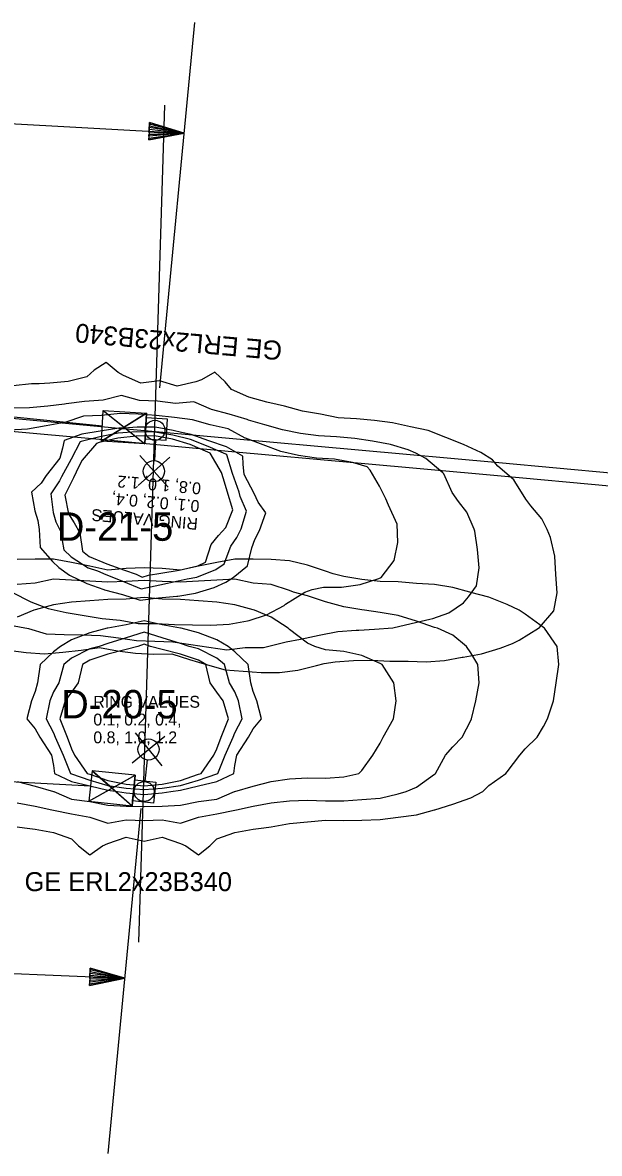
# Model space of a CAD drawing. Extents: x 1638506 to 1658005, y 834807 to 846788.
# Drawn here: x 1642969.6 to 1643212.7, y 842001.9 to 842479 of the extents above; entities that cross this region are included whole.
import ezdxf

# ---------------------------------------------------------------- set-up
doc = ezdxf.new("R2010")
doc.units = 0
for name, color, linetype in [('Default', 7, 'Continuous'), ('Exist Guardrail', 7, 'Continuous'), ('Old_Level_1', 7, 'Continuous'), ('Old_Level_2', 7, 'Continuous')]:
    doc.layers.add(name, color=color, linetype=linetype)

msp = doc.modelspace()

# ---------------------------------------------------------------- linework, layer by layer
at = {"layer": 'Default'}
for p, q in [((1643027.37, 842324.84), (1643042.12, 842478.96)), ((1642941.72, 842437.69), (1643037.67, 842432.39)), ((1642769.13, 842332.63), (1643003.18, 842308.79)), ((1643002.81, 842302.32), (1643021.8, 842314.24)), ((1643003.54, 842315.26), (1643021.07, 842301.3)), ((1643025.65, 842303.07), (1643025.15, 842294.14)), ((1643018.23, 842283.74), (1643031.58, 842295.64)), ((1643018.97, 842296.35), (1643030.87, 842283.03)), ((1643021.91, 842293.06), (1643021.91, 842293.06)), ((1643024.9, 842289.67), (1643024.9, 842289.67)), ((1643015.73, 842166.71), (1643029.59, 842177.98)), ((1643017, 842179.28), (1643028.3, 842165.42)), ((1642764.55, 842169.54), (1642998.17, 842156.92)), ((1643019.15, 842169.5), (1643019.15, 842169.5)), ((1643021.27, 842159.02), (1643022.19, 842167.92)), ((1643022.65, 842172.36), (1643022.65, 842172.36)), ((1642998.84, 842163.37), (1643015.7, 842148.6)), ((1642997.51, 842150.47), (1643017.03, 842161.49)), ((1643005.64, 842001.93), (1643019.57, 842147.37)), ((1642900.05, 842080.54), (1643012.72, 842075.81))]:
    msp.add_line(p, q, dxfattribs=at)
for points in [[(1643022.89, 842433.21), (1643022.93, 842433.95), (1643037.67, 842432.39), (1643022.97, 842434.64), (1643023.01, 842435.38), (1643037.67, 842432.39), (1643023.05, 842436.12), (1643023.09, 842436.85), (1643037.67, 842432.39), (1643022.74, 842429.51), (1643022.73, 842430.25), (1643037.67, 842432.39), (1643022.82, 842430.99), (1643022.81, 842431.73), (1643037.67, 842432.39), (1643022.85, 842432.47), (1643023.09, 842436.85), (1643022.74, 842429.51), (1643037.67, 842432.39), (1643023.09, 842436.85)], [(1643022.89, 842433.21), (1643022.93, 842433.95), (1643037.67, 842432.39), (1643022.97, 842434.64), (1643023.01, 842435.38), (1643037.67, 842432.39), (1643023.05, 842436.12), (1643023.09, 842436.85), (1643037.67, 842432.39), (1643022.74, 842429.51), (1643022.73, 842430.25), (1643037.67, 842432.39), (1643022.82, 842430.99), (1643022.81, 842431.73), (1643037.67, 842432.39), (1643022.85, 842432.47), (1643023.09, 842436.85), (1643022.74, 842429.51), (1643037.67, 842432.39), (1643023.09, 842436.85)], [(1642997.93, 842076.43), (1642997.97, 842077.17), (1643012.72, 842075.81), (1642997.99, 842077.86), (1642998.03, 842078.6), (1643012.72, 842075.81), (1642998.06, 842079.34), (1642998.09, 842080.08), (1643012.72, 842075.81), (1642997.83, 842072.73), (1642997.81, 842073.47), (1643012.72, 842075.81), (1642997.89, 842074.21), (1642997.87, 842074.95), (1643012.72, 842075.81), (1642997.9, 842075.69), (1642998.09, 842080.08), (1642997.83, 842072.73), (1643012.72, 842075.81), (1642998.09, 842080.08)]]:
    msp.add_lwpolyline(points, dxfattribs=at)
for points in [[(1643003.54, 842315.26), (1643021.8, 842314.24), (1643021.07, 842301.3), (1643002.81, 842302.32)], [(1643012.31, 842308.28), (1643002.81, 842302.32), (1643003.54, 842315.26)], [(1643012.31, 842308.28), (1643021.07, 842301.3), (1643021.8, 842314.24)], [(1643021.69, 842312.22), (1643021.19, 842303.32), (1643030.12, 842302.82), (1643030.62, 842311.72)], [(1642997.51, 842150.47), (1643015.7, 842148.6), (1643017.03, 842161.49), (1642998.84, 842163.37)], [(1643007.27, 842155.98), (1642998.84, 842163.37), (1642997.51, 842150.47)], [(1643007.27, 842155.98), (1643017.03, 842161.49), (1643015.7, 842148.6)], [(1643015.9, 842150.61), (1643016.82, 842159.48), (1643025.72, 842158.56), (1643024.8, 842149.69)]]:
    msp.add_lwpolyline(points, close=True, dxfattribs=at)
for centre in [(1643024.91, 842289.7), (1643022.65, 842172.33)]:
    msp.add_circle(centre, 4.47, dxfattribs=at)
at = {"layer": 'Exist Guardrail'}
msp.add_lwpolyline([(1642855.97, 842316.64), (1642901.48, 842312.43), (1642956.93, 842307.27), (1643008.14, 842302.6), (1643057.7, 842298.05), (1643110.69, 842293.31), (1643169.76, 842287.95), (1643218.45, 842283.37)], dxfattribs=at)
at = {"layer": 'Old_Level_1'}
for points in [[(1642963.51, 842214.19), (1642971.11, 842213.29), (1642978.73, 842212.63), (1642986.47, 842213.34), (1642994.23, 842214.26), (1643002, 842215.3), (1643009.56, 842213.88), (1643017.15, 842212.92), (1643024.8, 842212.55), (1643032.48, 842212.63), (1643039.96, 842210.25), (1643047.44, 842208.01), (1643054.94, 842205.96), (1643062.56, 842205.29), (1643070.2, 842204.85), (1643077.87, 842204.73), (1643085.64, 842205.81), (1643093.49, 842207.74), (1643096.73, 842208.6), (1643101.31, 842209.35), (1643109.04, 842209.9), (1643116.73, 842210.02), (1643124.37, 842209.56), (1643132.05, 842209.62), (1643139.7, 842209.3), (1643147.43, 842209.87), (1643154.79, 842211.2), (1643155.23, 842211.3), (1643163.04, 842212.71), (1643170.92, 842215.07), (1643176.12, 842217.02), (1643178.9, 842218.45), (1643187.01, 842223.43), (1643187.44, 842223.71), (1643193.49, 842230.86), (1643194.89, 842238.41), (1643194.33, 842246.14), (1643193.94, 842253.85), (1643192.11, 842261.69), (1643190.65, 842265.06), (1643188.44, 842269.69), (1643183.85, 842275.09), (1643181.74, 842277.96), (1643177.08, 842285.41), (1643176.63, 842286.09), (1643169.96, 842291.78), (1643167.58, 842294.56), (1643162.79, 842297.61), (1643155.4, 842300.98), (1643148.04, 842303.95), (1643147.98, 842303.97), (1643140.56, 842306.86), (1643133.02, 842308.48), (1643125.48, 842310.07), (1643117.89, 842311.07), (1643110.27, 842311.78), (1643102.64, 842312.3), (1643095.09, 842313.8), (1643087.53, 842315.11), (1643080.03, 842317.18), (1643076.94, 842317.84), (1643072.5, 842318.87), (1643065, 842320.92), (1643057.61, 842324.23), (1643054.99, 842327.44), (1643050.57, 842331.56), (1643044.94, 842328.32), (1643042.53, 842327.47), (1643034.68, 842325.55), (1643027.21, 842327.9), (1643019.44, 842326.89), (1643012.05, 842330.14), (1643009.83, 842331.4), (1643004.84, 842335.57), (1642999.78, 842332.27), (1642996.64, 842329.57), (1642988.79, 842327.59), (1642981.04, 842326.87), (1642976.49, 842326.63), (1642973.33, 842326.51), (1642965.59, 842325.78)], [(1642964.43, 842224.72), (1642971.99, 842223.38), (1642979.47, 842221.07), (1642987.12, 842220.78), (1642994.79, 842220.62), (1643002.45, 842220.4), (1643010.04, 842219.41), (1643017.63, 842218.35), (1643025.28, 842218.08), (1643032.93, 842217.73), (1643040.51, 842216.62), (1643048.09, 842215.44), (1643055.68, 842214.4), (1643063.44, 842215.38), (1643071.12, 842215.38), (1643078.96, 842217.25), (1643080.72, 842217.68), (1643086.78, 842218.8), (1643094.61, 842220.59), (1643102.43, 842222.1), (1643110.15, 842222.6), (1643111.26, 842222.69), (1643117.87, 842223.08), (1643125.6, 842223.63), (1643133.43, 842225.4), (1643141.28, 842227.33), (1643142.55, 842227.63), (1643149.18, 842229.92), (1643155.38, 842234.19), (1643157.46, 842236.74), (1643160.9, 842241.39), (1643162.04, 842248.97), (1643161.27, 842256.71), (1643160.23, 842264.48), (1643159.95, 842265.21), (1643156.89, 842272.45), (1643153.3, 842276.91), (1643150.63, 842280.68), (1643147.11, 842288.67), (1643146.68, 842289.07), (1643139.53, 842295.09), (1643135.38, 842297.37), (1643132.16, 842298.67), (1643124.69, 842301.05), (1643117.13, 842302.35), (1643109.55, 842303.57), (1643101.93, 842304.25), (1643094.29, 842304.62), (1643086.69, 842305.59), (1643079.15, 842307.14), (1643071.65, 842309.21), (1643064.86, 842311.22), (1643064.17, 842311.52), (1643056.69, 842313.73), (1643049.18, 842315.74), (1643041.79, 842318.97), (1643034.04, 842318.24), (1643026.45, 842319.2), (1643018.8, 842319.57), (1643011.3, 842321.64), (1643003.46, 842319.74), (1642995.72, 842319.06), (1642987.96, 842318.19), (1642987.24, 842318.01), (1642980.2, 842317.21), (1642972.46, 842316.47), (1642964.76, 842316.26)], [(1642965.63, 842238.46), (1642972.41, 842234.84), (1642972.97, 842234.62), (1642980.41, 842231.83), (1642987.94, 842230.1), (1642995.51, 842228.89), (1643003.08, 842227.64), (1643010.69, 842226.82), (1643018.24, 842225.42), (1643025.93, 842225.48), (1643033.56, 842224.98), (1643041.24, 842224.89), (1643048.9, 842224.77), (1643056.62, 842225.16), (1643064.42, 842226.62), (1643065.01, 842226.74), (1643072.32, 842229.13), (1643079.82, 842233.12), (1643080.4, 842233.63), (1643088.52, 842238.71), (1643091.65, 842239.77), (1643096.38, 842240.73), (1643104.06, 842240.81), (1643111.83, 842241.86), (1643119.74, 842244.52), (1643120.65, 842244.91), (1643126.23, 842252.1), (1643127.81, 842259.64), (1643127.42, 842267.35), (1643123.81, 842275.35), (1643122.68, 842278.05), (1643120.03, 842283.36), (1643116.05, 842290.1), (1643114.83, 842291.49), (1643108.67, 842293.45), (1643101.1, 842294.75), (1643093.47, 842295.27), (1643085.89, 842296.37), (1643078.36, 842298.08), (1643070.91, 842300.79), (1643063.48, 842303.62), (1643063.36, 842303.67), (1643056.15, 842307.54), (1643048.61, 842309.21), (1643041.12, 842311.35), (1643033.54, 842312.42), (1643025.93, 842313.26), (1643018.29, 842313.76), (1643010.64, 842314.01), (1643002.89, 842313.21), (1642995.18, 842312.88), (1642987.41, 842310.32), (1642987.27, 842310.29), (1642979.46, 842308.79), (1642971.66, 842307.42), (1642963.95, 842307.04)], [(1642974.71, 842273.03), (1642975.97, 842268.91), (1642976.57, 842265.19), (1642977.01, 842257.47), (1642982.13, 842251.56), (1642984.85, 842249.11), (1642989.32, 842245.92), (1642996.68, 842242.32), (1643003.81, 842239.77), (1643004.13, 842239.67), (1643011.64, 842237.66), (1643019.11, 842235.29), (1643026.88, 842236.32), (1643034.62, 842237), (1643034.95, 842237.05), (1643042.41, 842238.32), (1643050.29, 842240.59), (1643055.25, 842242.95), (1643058.34, 842244.89), (1643064.42, 842249.83), (1643066.2, 842257.35), (1643067.42, 842260.91), (1643069.39, 842264.75), (1643072.06, 842272.2), (1643068.8, 842276.67), (1643067.24, 842280.3), (1643062.9, 842288.36), (1643062.53, 842292.71), (1643062.38, 842296.08), (1643055.49, 842300.06), (1643048.03, 842302.58), (1643040.58, 842305.15), (1643036.58, 842306.02), (1643033.05, 842306.92), (1643025.49, 842308.26), (1643017.81, 842308.26), (1643014.18, 842307.98), (1643010.09, 842307.82), (1643002.31, 842306.58), (1642994.52, 842305.39), (1642987.05, 842302.67), (1642986.32, 842299.37), (1642985.2, 842295.15), (1642979.52, 842287.97), (1642977.35, 842284.67), (1642973.37, 842280.83), (1642974.71, 842273.03)], [(1642982.4, 842272.36), (1642983.61, 842268.37), (1642985.48, 842264.41), (1642986.96, 842256.6), (1642989.99, 842253.55), (1642997.27, 842249), (1643001.2, 842247.68), (1643004.7, 842246.17), (1643012.11, 842243.12), (1643019.53, 842240.07), (1643027.36, 842241.79), (1643035.18, 842243.51), (1643038.89, 842244.38), (1643042.99, 842245), (1643050.96, 842248.22), (1643054.47, 842250.7), (1643057.28, 842258.13), (1643059.81, 842261.7), (1643061.69, 842265.42), (1643063.89, 842272.91), (1643061.33, 842279.01), (1643060.79, 842280.86), (1643058.09, 842288.78), (1643055.61, 842296.67), (1643055.21, 842296.9), (1643047.82, 842300.17), (1643040.4, 842303.07), (1643032.88, 842304.95), (1643025.31, 842306.22), (1643017.64, 842306.29), (1643009.91, 842305.74), (1643002.1, 842304.17), (1642994.25, 842302.24), (1642993.82, 842302.08), (1642990.01, 842294.73), (1642985.97, 842287.41), (1642985.12, 842285.68), (1642981.53, 842280.12), (1642982.4, 842272.36)], [(1642988.88, 842271.79), (1642991.25, 842267.92), (1642993.66, 842263.7), (1642994.82, 842255.92), (1642997.68, 842253.74), (1643005.09, 842250.62), (1643012.54, 842247.97), (1643017.43, 842246.26), (1643019.96, 842245.08), (1643022.67, 842245.8), (1643027.78, 842246.64), (1643035.57, 842247.96), (1643043.41, 842249.74), (1643046.6, 842251.39), (1643049.1, 842258.85), (1643052.21, 842262.59), (1643055.22, 842265.99), (1643058.12, 842273.42), (1643055.73, 842281.3), (1643054.3, 842286.43), (1643053.35, 842289.19), (1643048.69, 842297.28), (1643047.61, 842297.76), (1643040.21, 842300.99), (1643032.73, 842303.2), (1643025.17, 842304.63), (1643017.49, 842304.53), (1643009.73, 842303.65), (1643001.89, 842301.76), (1643000.74, 842301.47), (1642994.74, 842294.32), (1642993.33, 842291.76), (1642991.03, 842286.96), (1642987.31, 842279.61), (1642988.88, 842271.79)], [(1643189.51, 842223.43), (1643189.11, 842223.74), (1643181.46, 842229.41), (1643178.82, 842231.08), (1643173.81, 842233.47), (1643166.16, 842236.51), (1643158.51, 842238.6), (1643158.08, 842238.73), (1643150.86, 842240.7), (1643143.21, 842241.94), (1643135.56, 842242.29), (1643127.91, 842243.02), (1643120.26, 842243.23), (1643112.61, 842244.02), (1643104.96, 842245.24), (1643100.46, 842246.38), (1643097.31, 842247.53), (1643089.66, 842250.13), (1643082.01, 842251.89), (1643074.36, 842252.43), (1643066.71, 842252.66), (1643059.06, 842252.66), (1643051.41, 842251.27), (1643043.76, 842249.69), (1643036.11, 842247.97), (1643028.46, 842248.73), (1643020.81, 842249.02), (1643013.16, 842248.73), (1643005.51, 842247.97), (1642997.86, 842249.69), (1642990.21, 842251.27), (1642982.56, 842252.66), (1642974.91, 842252.66), (1642967.26, 842252.43)], [(1643161.53, 842208.13), (1643158.51, 842213.06), (1643156.66, 842215.78), (1643150.86, 842220.57), (1643144.45, 842223.43), (1643143.21, 842223.85), (1643135.56, 842226.45), (1643127.91, 842228.9), (1643120.26, 842230.12), (1643113.72, 842231.08), (1643112.61, 842231.27), (1643104.96, 842232.44), (1643097.31, 842234.62), (1643089.66, 842237.1), (1643083.73, 842238.73), (1643082.01, 842239.32), (1643074.36, 842241.86), (1643066.71, 842242.54), (1643059.06, 842244.18), (1643051.41, 842243.81), (1643043.76, 842243.29), (1643036.11, 842242.85), (1643028.46, 842243.17), (1643020.81, 842243.56), (1643013.16, 842243.17), (1643005.51, 842242.85), (1642997.86, 842243.29), (1642990.21, 842243.81), (1642982.56, 842244.18), (1642974.91, 842242.54), (1642967.26, 842241.86)], [(1643121.13, 842208.13), (1643120.26, 842208.6), (1643112.61, 842211.94), (1643104.96, 842213.66), (1643097.31, 842214.41), (1643092.69, 842215.78), (1643089.66, 842217.11), (1643082.01, 842222.88), (1643081.49, 842223.43), (1643074.36, 842228.07), (1643067.29, 842231.08), (1643066.71, 842231.25), (1643059.06, 842233.38), (1643051.41, 842234.45), (1643043.76, 842235), (1643036.11, 842235.58), (1643028.46, 842235.74), (1643020.81, 842236.47), (1643013.16, 842235.74), (1643005.51, 842235.58), (1642997.86, 842235), (1642990.21, 842234.45), (1642982.56, 842233.38), (1642974.91, 842231.25), (1642974.34, 842231.08), (1642967.26, 842228.07)], [(1643068.33, 842192.83), (1643066.71, 842196.83), (1643065.8, 842200.48), (1643064.69, 842208.13), (1643059.06, 842213.58), (1643056.15, 842215.78), (1643051.41, 842218.57), (1643043.76, 842221.52), (1643036.44, 842223.43), (1643036.11, 842223.51), (1643028.46, 842224.86), (1643020.81, 842226.57), (1643013.16, 842224.86), (1643005.51, 842223.51), (1643005.18, 842223.43), (1642997.86, 842221.52), (1642990.21, 842218.57), (1642985.48, 842215.78), (1642982.56, 842213.58), (1642976.94, 842208.13), (1642975.83, 842200.48), (1642974.91, 842196.83), (1642973.29, 842192.83), (1642971.28, 842185.18), (1642974.91, 842181.01), (1642976.78, 842177.53), (1642981.81, 842169.88), (1642982.56, 842165.58), (1642983, 842162.23), (1642990.21, 842158.87), (1642997.86, 842157.01), (1643005.51, 842155.09), (1643009.57, 842154.58), (1643013.16, 842153.99), (1643020.81, 842153.31), (1643028.46, 842153.99), (1643032.05, 842154.58), (1643036.11, 842155.09), (1643043.76, 842157.01), (1643051.41, 842158.87), (1643058.62, 842162.23), (1643059.06, 842165.58), (1643059.81, 842169.88), (1643064.84, 842177.53), (1643066.71, 842181.01), (1643070.34, 842185.18), (1643068.33, 842192.83)], [(1642967.26, 842139.68), (1642970.39, 842139.28), (1642974.91, 842138.65), (1642982.56, 842137.26), (1642990.21, 842134.6), (1642993.1, 842131.63), (1642997.86, 842127.91), (1643003.19, 842131.63), (1643005.51, 842132.69), (1643013.16, 842135.29), (1643020.81, 842133.6), (1643028.46, 842135.29), (1643036.11, 842132.69), (1643038.44, 842131.63), (1643043.76, 842127.91), (1643048.52, 842131.63), (1643051.41, 842134.6), (1643059.06, 842137.26), (1643066.71, 842138.65), (1643071.23, 842139.28), (1643074.36, 842139.68), (1643082.01, 842141.08), (1643089.66, 842141.73), (1643097.31, 842142.57), (1643104.96, 842142.42), (1643112.61, 842142.46), (1643120.26, 842142.8), (1643127.91, 842143.72), (1643135.56, 842144.69), (1643143.21, 842146.92), (1643143.27, 842146.93), (1643150.86, 842149.25), (1643158.51, 842151.96), (1643163.55, 842154.58), (1643166.16, 842157.14), (1643173.3, 842162.23), (1643173.81, 842162.87), (1643179.11, 842169.88), (1643181.46, 842172.55), (1643186.51, 842177.53), (1643189.11, 842181.96), (1643190.86, 842185.18), (1643193.36, 842192.83), (1643194.42, 842200.48), (1643195.65, 842208.13), (1643194.92, 842215.78), (1643189.51, 842223.43)], [(1643060.61, 842192.83), (1643059.06, 842196.7), (1643056.85, 842200.48), (1643054.7, 842208.13), (1643051.41, 842210.91), (1643043.76, 842214.81), (1643039.73, 842215.78), (1643036.11, 842216.98), (1643028.46, 842219.37), (1643020.81, 842221.76), (1643013.16, 842219.37), (1643005.51, 842216.98), (1643001.9, 842215.78), (1642997.86, 842214.81), (1642990.21, 842210.91), (1642986.93, 842208.13), (1642984.77, 842200.48), (1642982.56, 842196.7), (1642981.02, 842192.83), (1642979.47, 842185.18), (1642982.56, 842179.33), (1642983.26, 842177.53), (1642986.64, 842169.88), (1642989.8, 842162.23), (1642990.21, 842162.04), (1642997.86, 842159.43), (1643005.51, 842157.19), (1643013.16, 842155.97), (1643020.81, 842155.37), (1643028.46, 842155.97), (1643036.11, 842157.19), (1643043.76, 842159.43), (1643051.41, 842162.04), (1643051.83, 842162.23), (1643054.98, 842169.88), (1643058.36, 842177.53), (1643059.06, 842179.33), (1643062.15, 842185.18), (1643060.61, 842192.83)], [(1643054.11, 842192.83), (1643051.41, 842196.48), (1643048.63, 842200.48), (1643046.8, 842208.13), (1643043.76, 842210.05), (1643036.11, 842212.51), (1643028.46, 842214.5), (1643023.44, 842215.78), (1643020.81, 842216.73), (1643018.18, 842215.78), (1643013.16, 842214.5), (1643005.51, 842212.51), (1642997.86, 842210.05), (1642994.82, 842208.13), (1642992.99, 842200.48), (1642990.21, 842196.48), (1642987.52, 842192.83), (1642985.27, 842185.18), (1642988.33, 842177.53), (1642990.21, 842172.55), (1642991.39, 842169.88), (1642996.74, 842162.23), (1642997.86, 842161.84), (1643005.51, 842159.28), (1643013.16, 842157.73), (1643020.81, 842156.96), (1643028.46, 842157.73), (1643036.11, 842159.28), (1643043.76, 842161.84), (1643044.88, 842162.23), (1643050.23, 842169.88), (1643051.41, 842172.55), (1643053.29, 842177.53), (1643056.35, 842185.18), (1643054.11, 842192.83)], [(1642967.26, 842149.76), (1642974.91, 842148.34), (1642981.86, 842146.93), (1642982.56, 842146.69), (1642990.21, 842145.15), (1642997.86, 842143.8), (1643005.51, 842141.22), (1643013.16, 842142.63), (1643020.81, 842142.33), (1643028.46, 842142.63), (1643036.11, 842141.22), (1643043.76, 842143.8), (1643051.41, 842145.15), (1643059.06, 842146.69), (1643059.77, 842146.93), (1643066.71, 842148.34), (1643074.36, 842149.76), (1643082.01, 842150.64), (1643089.66, 842150.94), (1643097.31, 842150.65), (1643104.96, 842150.66), (1643112.61, 842151.21), (1643120.26, 842151.85), (1643127.91, 842153.57), (1643131.23, 842154.58), (1643135.56, 842156.49), (1643143.21, 842161.87), (1643143.67, 842162.23), (1643147.88, 842169.88), (1643150.86, 842173.4), (1643154.83, 842177.53), (1643158.51, 842184.48), (1643158.86, 842185.18), (1643160.57, 842192.83), (1643162.01, 842200.48), (1643161.53, 842208.13)], [(1642967.26, 842158.85), (1642974.91, 842156.8), (1642982.56, 842154.63), (1642982.69, 842154.58), (1642990.21, 842151.36), (1642997.86, 842150.36), (1643005.51, 842148.88), (1643013.16, 842148.47), (1643020.81, 842148.3), (1643028.46, 842148.47), (1643036.11, 842148.88), (1643043.76, 842150.36), (1643051.41, 842151.36), (1643058.93, 842154.58), (1643059.06, 842154.63), (1643066.71, 842156.8), (1643074.36, 842158.85), (1643082.01, 842159.9), (1643089.66, 842160.33), (1643097.31, 842160.19), (1643104.96, 842160.82), (1643111.27, 842162.23), (1643112.61, 842163.51), (1643117.16, 842169.88), (1643120.26, 842174.94), (1643121.62, 842177.53), (1643125.92, 842185.18), (1643126.98, 842192.83), (1643126.06, 842200.48), (1643121.13, 842208.13)]]:
    msp.add_lwpolyline(points, dxfattribs=at)
for centre in [(1643025.38, 842307), (1643020.81, 842154.58)]:
    msp.add_circle(centre, 4.21, dxfattribs=at)
at = {"layer": 'Old_Level_2'}
msp.add_line((1643018.55, 842090.97), (1643029.58, 842444.14), dxfattribs=at)
msp.add_lwpolyline([(1642661.86, 842343.82), (1642901.99, 842317.91), (1642957.43, 842312.75), (1643008.64, 842308.08), (1643058.2, 842303.53), (1643111.19, 842298.79), (1643170.27, 842293.42), (1643218.96, 842288.85)], dxfattribs=at)

# ---------------------------------------------------------------- texts
at = {"layer": 'Default'}
for s, p in [('D-21-5', (1642984.02, 842260.36)), ('D-20-5', (1642985.85, 842185.42))]:
    msp.add_text(s, height=12, dxfattribs=at).set_placement(p)
at = {"layer": 'Old_Level_1'}
for s, height, p in [('GE ERL2x23B340', 8, (1643079.26, 842344.46)), ('0.8, 1.0, 1.2', 5, (1643044.95, 842284.85)), ('0.1, 0.2, 0.4,', 5, (1643044.3, 842277.38)), ('RING VALUES', 5, (1643043.64, 842269.91))]:
    msp.add_text(s, height=height, rotation=175, dxfattribs=at).set_placement(p)
for s, height, p in [('RING VALUES', 5, (1642999.39, 842189.94)), ('0.1, 0.2, 0.4,', 5, (1642999.39, 842182.44)), ('0.8, 1.0, 1.2', 5, (1642999.39, 842174.94)), ('GE ERL2x23B340', 8, (1642970.4, 842112.56))]:
    msp.add_text(s, height=height, dxfattribs=at).set_placement(p)

doc.saveas('drawing.dxf')
